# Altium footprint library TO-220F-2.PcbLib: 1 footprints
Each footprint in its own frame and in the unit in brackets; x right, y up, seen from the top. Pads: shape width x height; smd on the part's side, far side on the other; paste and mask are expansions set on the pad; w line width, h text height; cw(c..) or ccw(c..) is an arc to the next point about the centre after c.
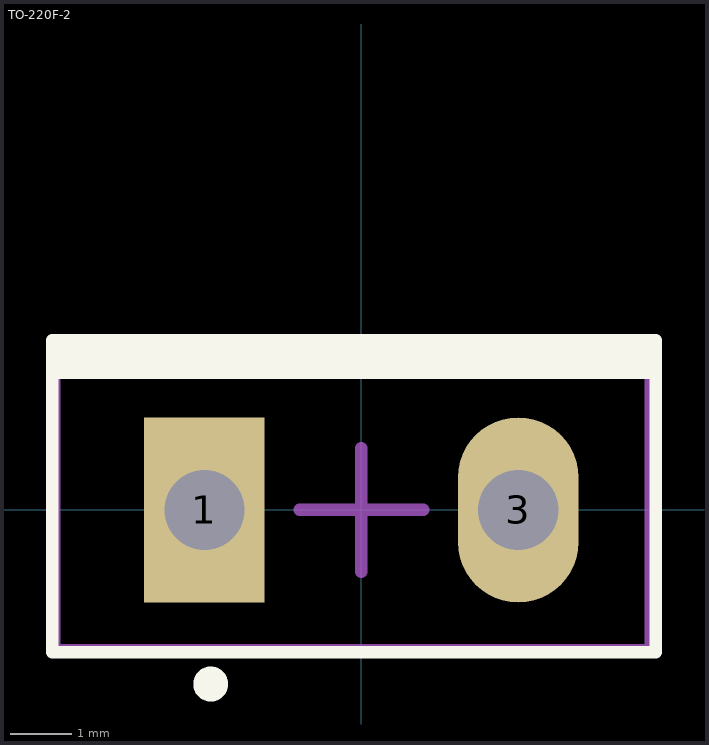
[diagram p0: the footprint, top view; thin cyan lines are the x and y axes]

## TO-220F-2 [mm] "10mm x 4.4mm"
height 15.65
pads (2):
  rect 1.95x3 hole 1.3: 1(-2.54,0)
  oval 1.95x3 hole 1.3: 3(2.54,0)
Top Overlay:
  circle w0.3: c-2.438,-2.819 r0.132
  region: 4.828,2.122 4.828,2.746 -5.007,2.746 -5.007,2.122
  lines w0.2: -5.007,-2.303 -5.007,2.746 4.769,2.746 4.769,-2.303 -5.007,-2.303
Mechanical 15:
  lines w0.2: -1,0 1,0 ; 0,-1 0,1 ; -4.967,-2.274 4.681,-2.274 4.681,2.687 -4.967,2.687 -4.967,-2.274
3D body "TO-220-2.step": height 18.3, standoff -10.08, extent -4.877,-2.362 4.775,2.138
